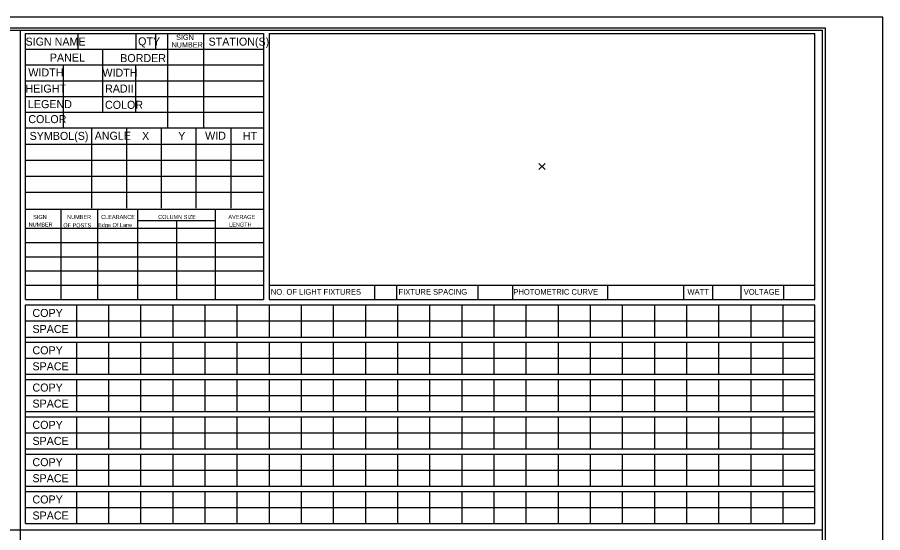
# Model space of a CAD drawing. Extents: x 121688 to 126625, y -22764 to -19972.
# Drawn here: x 125847 to 126625, y -22218 to -21754 of the extents above; entities that cross this region are included whole.
import ezdxf

# ---------------------------------------------------------------- set-up
doc = ezdxf.new("R2010")
doc.units = 0
for name, color, linetype in [('NonPlottingEle_dp', 7, 'Continuous'), ('PlotBorder_dp', 7, 'Continuous'), ('SheetBorder_dp', 7, 'Continuous'), ('SheetLinesMisc2_dp', 7, 'Continuous'), ('TextMinor', 7, 'Continuous')]:
    doc.layers.add(name, color=color, linetype=linetype)

msp = doc.modelspace()

# ---------------------------------------------------------------- linework, layer by layer
at = {"layer": 'NonPlottingEle_dp'}
for p, q in [((126315.84, -21885.68), (126321.44, -21891.28)), ((126315.84, -21891.28), (126321.44, -21885.68))]:
    msp.add_line(p, q, dxfattribs=at)
at = {"layer": 'PlotBorder_dp'}
msp.add_lwpolyline([(125072.61, -22751.63), (126625.18, -22751.63), (126625.18, -21754.22), (125072.61, -21754.22)], close=True, dxfattribs=at)
at = {"layer": 'SheetBorder_dp'}
for p, q in [((125124.37, -21763.63), (126573.42, -21763.63)), ((126573.42, -21763.63), (126573.42, -22742.22))]:
    msp.add_line(p, q, dxfattribs=at)
at = {"layer": 'SheetLinesMisc2_dp'}
for p, q in [((125126.93, -21765.86), (126571.13, -21765.86)), ((125849.03, -21765.86), (125849.03, -22664.86)), ((125853.96, -22008.11), (125853.96, -21768.85)), ((125853.96, -21768.85), (126068.1, -21768.85)), ((125901.16, -21768.85), (125901.16, -21782.98)), ((125953.22, -21768.85), (125953.22, -21782.98)), ((125971, -21768.85), (125971, -21782.98)), ((125981.59, -21768.85), (125981.59, -21853.65)), ((126014.18, -21768.85), (126014.18, -21853.65)), ((126068.1, -21768.85), (126068.1, -22008.11)), ((126073.04, -21768.85), (126564.23, -21768.85)), ((126073.04, -21768.85), (126073.04, -22008.11)), ((126564.23, -22008.11), (126564.23, -21768.85)), ((126571.14, -22664.87), (126571.14, -21765.86)), ((125853.96, -21782.98), (126068.1, -21782.98)), ((125923.17, -21782.98), (125923.17, -21839.66)), ((125853.96, -21797.12), (126068.1, -21797.12)), ((125887.8, -21797.12), (125887.8, -21853.65)), ((125953.03, -21797.27), (125953.03, -21839.66)), ((125853.96, -21811.25), (126068.1, -21811.25)), ((125853.96, -21825.38), (126068.1, -21825.38)), ((125853.96, -21839.51), (125933.38, -21839.51)), ((125923.17, -21839.66), (125981.59, -21839.66)), ((125981.59, -21839.51), (126068.1, -21839.51)), ((125853.96, -21853.65), (126068.1, -21853.65)), ((125913.43, -21853.93), (125913.43, -21926.08)), ((125944.72, -21853.93), (125944.72, -21926.08)), ((125976.01, -21853.93), (125976.01, -21926.08)), ((126007.3, -21853.93), (126007.3, -21926.08)), ((126038.59, -21853.93), (126038.59, -21926.08)), ((125854.01, -21868.36), (126068.1, -21868.36)), ((125854.01, -21882.79), (126068.1, -21882.79)), ((125854.01, -21897.21), (126068.1, -21897.21)), ((125854.01, -21911.65), (126068.1, -21911.65)), ((125853.96, -21926.77), (126068.1, -21926.77)), ((125885.74, -21926.77), (125885.74, -22008.11)), ((125918.58, -21926.77), (125918.58, -22008.11)), ((125954.84, -21926.77), (125954.84, -22008.11)), ((126024.68, -21926.77), (126024.68, -22008.11)), ((125954.84, -21937.11), (126024.63, -21937.11)), ((125989.9, -21937.11), (125989.9, -22008.11)), ((125853.96, -21944.01), (126068.1, -21944.01)), ((125853.96, -21956.83), (126068.1, -21956.83)), ((125853.96, -21969.65), (126068.1, -21969.65)), ((125853.96, -21982.47), (126068.1, -21982.47)), ((125853.96, -21995.29), (126068.1, -21995.29)), ((126073.04, -21995.29), (126564.23, -21995.29)), ((126167.92, -21995.29), (126167.92, -22008.11)), ((126187.79, -21995.29), (126187.79, -22008.11)), ((126260.93, -21995.29), (126260.93, -22008.11)), ((126292.06, -21995.29), (126292.06, -22008.11)), ((126377.58, -21995.29), (126377.58, -22008.11)), ((126445.84, -21995.29), (126445.84, -22008.11)), ((126472.19, -21995.29), (126472.19, -22008.11)), ((126497.6, -21995.29), (126497.6, -22008.11)), ((126535.86, -21995.29), (126535.86, -22008.11)), ((125853.96, -22008.11), (126068.1, -22008.11)), ((126073.04, -22008.11), (126564.23, -22008.11)), ((125853.96, -22209.69), (125853.96, -22013.04)), ((125853.96, -22013.04), (126564.23, -22013.04)), ((125899.69, -22013.04), (125899.69, -22041.9)), ((125928.58, -22013.04), (125928.58, -22041.9)), ((125957.47, -22013.04), (125957.47, -22041.9)), ((125986.36, -22013.04), (125986.36, -22041.9)), ((126015.27, -22013.04), (126015.27, -22041.9)), ((126044.15, -22013.04), (126044.15, -22041.9)), ((126073.04, -22013.04), (126073.04, -22041.9)), ((126101.94, -22013.04), (126101.94, -22041.9)), ((126130.83, -22013.04), (126130.83, -22041.9)), ((126159.73, -22013.04), (126159.73, -22041.9)), ((126188.62, -22013.04), (126188.62, -22041.9)), ((126217.51, -22013.04), (126217.51, -22041.9)), ((126246.41, -22013.04), (126246.41, -22041.9)), ((126275.3, -22013.04), (126275.3, -22041.9)), ((126304.19, -22013.04), (126304.19, -22041.9)), ((126333.08, -22013.04), (126333.08, -22041.9)), ((126361.98, -22013.04), (126361.98, -22041.9)), ((126390.87, -22013.04), (126390.87, -22041.9)), ((126419.76, -22013.04), (126419.76, -22041.9)), ((126448.65, -22013.04), (126448.65, -22041.9)), ((126477.55, -22013.04), (126477.55, -22041.9)), ((126506.45, -22013.04), (126506.45, -22041.9)), ((126535.34, -22013.04), (126535.34, -22041.9)), ((126564.23, -22209.69), (126564.23, -22013.04)), ((125853.96, -22027.46), (126564.23, -22027.46)), ((125853.96, -22041.9), (126564.23, -22041.9)), ((125853.96, -22046.6), (126564.23, -22046.6)), ((125899.69, -22046.6), (125899.69, -22075.45)), ((125928.58, -22046.6), (125928.58, -22075.45)), ((125957.47, -22046.6), (125957.47, -22075.45)), ((125986.36, -22046.6), (125986.36, -22075.45)), ((126015.27, -22046.6), (126015.27, -22075.45)), ((126044.15, -22046.6), (126044.15, -22075.45)), ((126073.04, -22046.6), (126073.04, -22075.45)), ((126101.94, -22046.6), (126101.94, -22075.45)), ((126130.83, -22046.6), (126130.83, -22075.45)), ((126159.73, -22046.6), (126159.73, -22075.45)), ((126188.62, -22046.6), (126188.62, -22075.45)), ((126217.51, -22046.6), (126217.51, -22075.45)), ((126246.41, -22046.6), (126246.41, -22075.45)), ((126275.3, -22046.6), (126275.3, -22075.45)), ((126304.19, -22046.6), (126304.19, -22075.45)), ((126333.08, -22046.6), (126333.08, -22075.45)), ((126361.98, -22046.6), (126361.98, -22075.45)), ((126390.87, -22046.6), (126390.87, -22075.45)), ((126419.76, -22046.6), (126419.76, -22075.45)), ((126448.65, -22046.6), (126448.65, -22075.45)), ((126477.55, -22046.6), (126477.55, -22075.45)), ((126506.45, -22046.6), (126506.45, -22075.45)), ((126535.34, -22046.6), (126535.34, -22075.45)), ((125853.96, -22061.03), (126564.23, -22061.02)), ((125853.96, -22075.45), (126564.23, -22075.45)), ((125853.96, -22080.16), (126564.23, -22080.16)), ((125899.69, -22080.16), (125899.69, -22109.01)), ((125928.58, -22080.16), (125928.58, -22109.01)), ((125957.47, -22080.16), (125957.47, -22109.01)), ((125986.36, -22080.16), (125986.36, -22109.01)), ((126015.27, -22080.16), (126015.27, -22109.01)), ((126044.15, -22080.16), (126044.15, -22109.01)), ((126073.04, -22080.16), (126073.04, -22109.01)), ((126101.94, -22080.16), (126101.94, -22109.01)), ((126130.83, -22080.16), (126130.83, -22109.01)), ((126159.73, -22080.16), (126159.73, -22109.01)), ((126188.62, -22080.16), (126188.62, -22109.01)), ((126217.51, -22080.16), (126217.51, -22109.01)), ((126246.41, -22080.16), (126246.41, -22109.01)), ((126275.3, -22080.16), (126275.3, -22109.01)), ((126304.19, -22080.16), (126304.19, -22109.01)), ((126333.08, -22080.16), (126333.08, -22109.01)), ((126361.98, -22080.16), (126361.98, -22109.01)), ((126390.87, -22080.16), (126390.87, -22109.01)), ((126419.76, -22080.16), (126419.76, -22109.01)), ((126448.65, -22080.16), (126448.65, -22109.01)), ((126477.55, -22080.16), (126477.55, -22109.01)), ((126506.45, -22080.16), (126506.45, -22109.01)), ((126535.34, -22080.16), (126535.34, -22109.01)), ((125853.96, -22094.59), (126564.23, -22094.59)), ((125853.96, -22109.01), (126564.23, -22109.01)), ((125853.96, -22113.72), (126564.23, -22113.72)), ((125899.69, -22113.72), (125899.69, -22142.58)), ((125928.58, -22113.72), (125928.58, -22142.58)), ((125957.47, -22113.72), (125957.47, -22142.58)), ((125986.36, -22113.72), (125986.36, -22142.58)), ((126015.27, -22113.72), (126015.27, -22142.58)), ((126044.15, -22113.72), (126044.15, -22142.58)), ((126073.04, -22113.72), (126073.04, -22142.58)), ((126101.94, -22113.72), (126101.94, -22142.58)), ((126130.83, -22113.72), (126130.83, -22142.58)), ((126159.73, -22113.72), (126159.73, -22142.58)), ((126188.62, -22113.72), (126188.62, -22142.58)), ((126217.51, -22113.72), (126217.51, -22142.58)), ((126246.41, -22113.72), (126246.41, -22142.58)), ((126275.3, -22113.72), (126275.3, -22142.58)), ((126304.19, -22113.72), (126304.19, -22142.58)), ((126333.08, -22113.72), (126333.08, -22142.58)), ((126361.98, -22113.72), (126361.98, -22142.58)), ((126390.87, -22113.72), (126390.87, -22142.58)), ((126419.76, -22113.72), (126419.76, -22142.58)), ((126448.65, -22113.72), (126448.65, -22142.58)), ((126477.55, -22113.72), (126477.55, -22142.58)), ((126506.45, -22113.72), (126506.45, -22142.58)), ((126535.34, -22113.72), (126535.34, -22142.58)), ((125853.96, -22128.15), (126564.23, -22128.15)), ((125853.96, -22142.58), (126564.23, -22142.58)), ((125853.96, -22147.28), (126564.23, -22147.28)), ((125899.69, -22147.28), (125899.69, -22176.14)), ((125928.58, -22147.28), (125928.58, -22176.14)), ((125957.47, -22147.28), (125957.47, -22176.14)), ((125986.36, -22147.28), (125986.36, -22176.14)), ((126015.27, -22147.28), (126015.27, -22176.14)), ((126044.15, -22147.28), (126044.15, -22176.14)), ((126073.04, -22147.28), (126073.04, -22176.14)), ((126101.94, -22147.28), (126101.94, -22176.14)), ((126130.83, -22147.28), (126130.83, -22176.14)), ((126159.73, -22147.28), (126159.73, -22176.14)), ((126188.62, -22147.28), (126188.62, -22176.14)), ((126217.51, -22147.28), (126217.51, -22176.14)), ((126246.41, -22147.28), (126246.41, -22176.14)), ((126275.3, -22147.28), (126275.3, -22176.14)), ((126304.19, -22147.28), (126304.19, -22176.14)), ((126333.08, -22147.28), (126333.08, -22176.14)), ((126361.98, -22147.28), (126361.98, -22176.14)), ((126390.87, -22147.28), (126390.87, -22176.14)), ((126419.76, -22147.28), (126419.76, -22176.14)), ((126448.65, -22147.28), (126448.65, -22176.14)), ((126477.55, -22147.28), (126477.55, -22176.14)), ((126506.45, -22147.28), (126506.45, -22176.14)), ((126535.34, -22147.28), (126535.34, -22176.14)), ((125853.96, -22161.71), (126564.23, -22161.71)), ((125853.96, -22176.14), (126564.23, -22176.14)), ((125853.96, -22180.84), (126564.23, -22180.84)), ((125899.69, -22180.84), (125899.69, -22209.69)), ((125928.58, -22180.84), (125928.58, -22209.69)), ((125957.47, -22180.84), (125957.47, -22209.69)), ((125986.36, -22180.84), (125986.36, -22209.69)), ((126015.27, -22180.84), (126015.27, -22209.69)), ((126044.15, -22180.84), (126044.15, -22209.69)), ((126073.04, -22180.84), (126073.04, -22209.69)), ((126101.94, -22180.84), (126101.94, -22209.69)), ((126130.83, -22180.84), (126130.83, -22209.69)), ((126159.73, -22180.84), (126159.73, -22209.69)), ((126188.62, -22180.84), (126188.62, -22209.69)), ((126217.51, -22180.84), (126217.51, -22209.69)), ((126246.41, -22180.84), (126246.41, -22209.69)), ((126275.3, -22180.84), (126275.3, -22209.69)), ((126304.19, -22180.84), (126304.19, -22209.69)), ((126333.08, -22180.84), (126333.08, -22209.69)), ((126361.98, -22180.84), (126361.98, -22209.69)), ((126390.87, -22180.84), (126390.87, -22209.69)), ((126419.76, -22180.84), (126419.76, -22209.69)), ((126448.65, -22180.84), (126448.65, -22209.69)), ((126477.55, -22180.84), (126477.55, -22209.69)), ((126506.45, -22180.84), (126506.45, -22209.69)), ((126535.34, -22180.84), (126535.34, -22209.69)), ((125853.96, -22195.26), (126564.23, -22195.26)), ((125853.96, -22209.69), (126564.23, -22209.69)), ((125126.93, -22215.36), (126571.13, -22215.36))]:
    msp.add_line(p, q, dxfattribs=at)

# ---------------------------------------------------------------- texts
at = {"layer": 'TextMinor'}
for s, height, p in [('SIGN NAME', 7.199, (125853.96, -21779.67)), ('QTY', 7.199, (125955.27, -21779.44)), ('NUMBER', 4.705, (125985.37, -21781.36)), ('SIGN', 4.705, (125989.46, -21774.52)), ('STATION(S)', 7.199, (126018.67, -21779.71)), ('PANEL', 7.199, (125875.85, -21794.03)), ('BORDER', 7.199, (125939.17, -21794.52)), ('WIDTH', 7.199, (125856.5, -21807.48)), ('WIDTH', 7.199, (125923.17, -21807.63)), ('HEIGHT', 7.199, (125853.96, -21821.97)), ('RADII', 7.199, (125925.53, -21821.94)), ('LEGEND', 7.199, (125856.13, -21835.95)), ('COLOR', 7.199, (125925.48, -21836.56)), ('COLOR', 7.199, (125856.5, -21849.43)), ('SYMBOL(S)', 7.199, (125857.65, -21864.54)), ('ANGLE', 7.199, (125916.18, -21864.39)), ('X', 7.2, (125958.8, -21864.54)), ('Y', 7.2, (125991.33, -21864.54)), ('WID', 7.199, (126015.56, -21864.39)), ('HT', 7.199, (126049.48, -21864.52)), ('SIGN', 3.6, (125860.83, -21935.65)), ('NUMBER', 3.6, (125891.39, -21935.69)), ('CLEARANCE', 3.6, (125922.04, -21935.66)), ('COLUMN SIZE', 3.5997, (125973.34, -21935.66)), ('AVERAGE', 3.6, (126036.48, -21935.66)), ('NUMBER', 3.6, (125856.79, -21942.49)), ('OF POSTS', 3.6, (125887.99, -21943.17)), ('Edge Of Lane', 3.5997, (125919.26, -21942.91)), ('LENGTH', 3.6, (126037.16, -21942.49)), ('NO. OF LIGHT FIXTURES', 5.102, (126074.69, -22003.82)), ('FIXTURE SPACING', 5.102, (126189.56, -22003.82)), ('PHOTOMETRIC CURVE', 5.102, (126292.87, -22003.82)), ('WATT', 5.102, (126449.5, -22003.82)), ('VOLTAGE', 5.102, (126500.15, -22003.82)), ('COPY', 7.199, (125860.21, -22023.83)), ('SPACE', 7.199, (125860.21, -22038.26)), ('COPY', 7.199, (125860.21, -22057.39)), ('SPACE', 7.199, (125860.21, -22071.81)), ('COPY', 7.199, (125860.21, -22090.95)), ('SPACE', 7.199, (125860.21, -22105.38)), ('COPY', 7.199, (125860.21, -22124.51)), ('SPACE', 7.199, (125860.21, -22138.94)), ('COPY', 7.199, (125860.21, -22158.08)), ('SPACE', 7.199, (125860.21, -22172.51)), ('COPY', 7.199, (125860.21, -22191.63)), ('SPACE', 7.199, (125860.21, -22206.06))]:
    msp.add_text(s, height=height, dxfattribs=at).set_placement(p)

doc.saveas('drawing.dxf')
